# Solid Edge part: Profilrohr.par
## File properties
Dokumentum tartalom típus: 0
Last saved by: bmolnar
Revision: 77
Sűrűség: 0,000 kg/m^3
Pontosság: 0,990
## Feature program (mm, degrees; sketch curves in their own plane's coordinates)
base feature "unnamed BaseFeature 1"
thread "unnamed Thread 1"
thread "Menet_2"  ThreadDepth = 6 mm
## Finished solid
Body 1: solid body, 143 faces, 298 edges, 218 vertices, 3 separate solids.
  Faces by surface: plane 62, cylinder 61, cone 16, torus 4
  Edges by curve: line 156, circle 138, curve on surface 2, spline 2
Bounding box of the edges (mm; curved faces can reach further): 46.000 x 51.000 x 44.500, from (-23, -24, 0) to (23, 27, 44.5).
Cylindrical faces by radius (mm): R0.3 x24, R0.8 x2, R2.5 x2, R2.9 x8, R4.283 x4, R4.35 x2, R4.4 x6, R4.5 x2, R16 x1, R16.85 x2, R17.05 x2, R17.9 x2, R30 x4
Conical faces (half-angle, radius in mm at the cone's reference point): 21 deg R16.325 x2, 30 deg R4.0613 x2, 45 deg R2.75 x4, 45 deg R4.1 x2, 45 deg R4.783 x2, 45 deg R17.1 x2, 45 deg R17.15 x2
Toroidal faces (ring radius, tube radius in mm): R17.7 r0.2 x4
Planar faces by outward normal: +x 6, +y 9, +z 10, -x 6, -y 5, -z 10, oblique 16
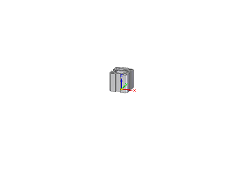
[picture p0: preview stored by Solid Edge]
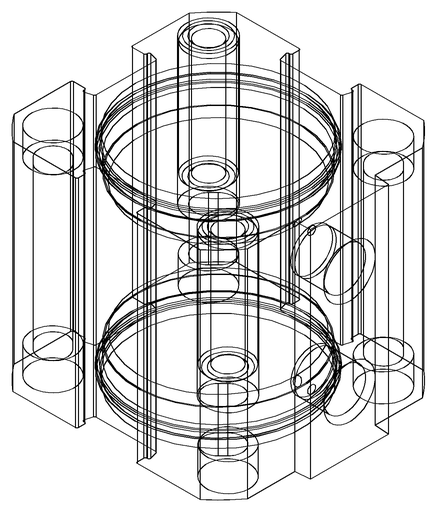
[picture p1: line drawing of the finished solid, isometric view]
